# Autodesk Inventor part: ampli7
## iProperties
Created: 2009-06
Part Number: ampli7
Document SubType Name: Modeling
Designer: ajtco
Manufacturer: Standard
Standards Organization: Custom
Author: ajtco
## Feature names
1. Extrusion1
